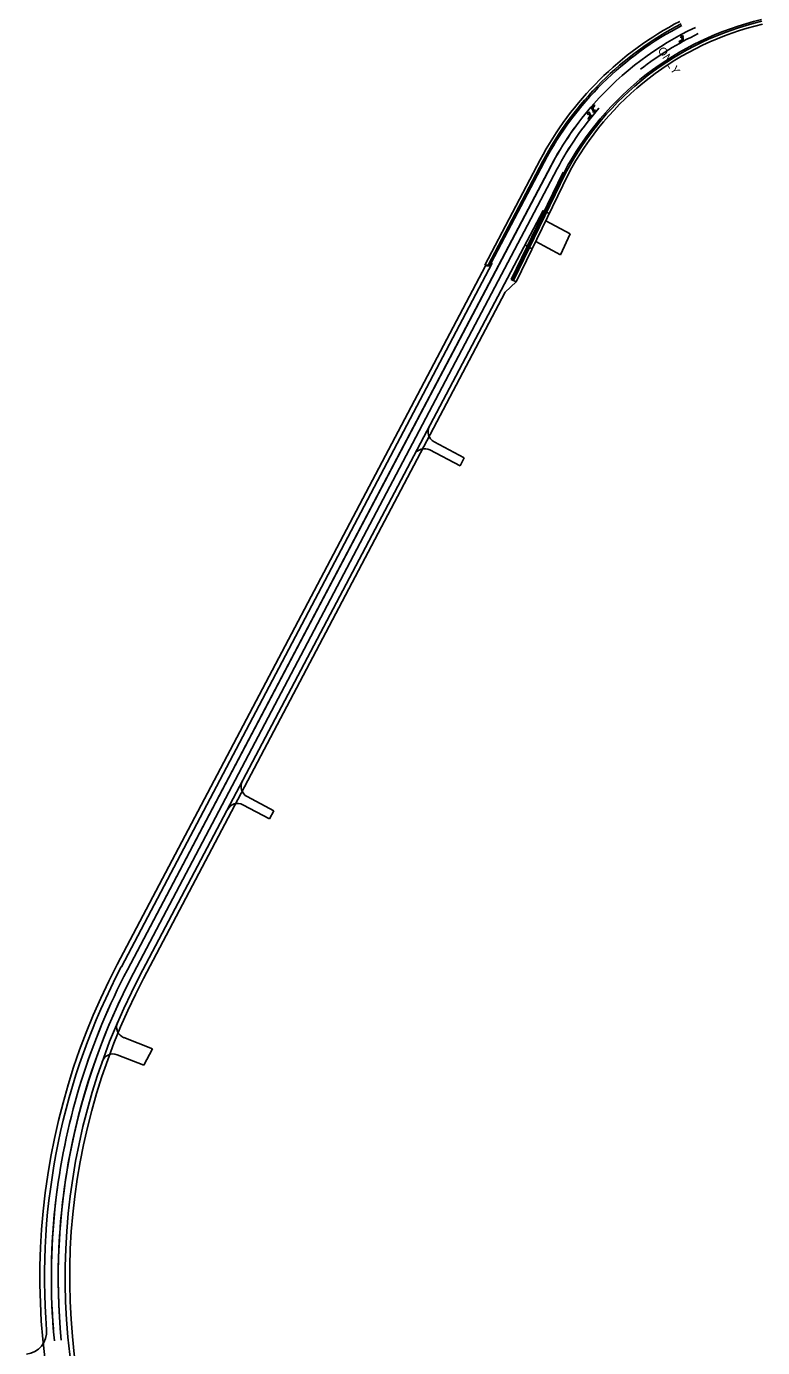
# Model space of a CAD drawing. Extents: x 979036 to 996074, y 1836928 to 1845163.
# Drawn here: x 980536 to 981821, y 1839457 to 1841763 of the extents above; entities that cross this region are included whole.
import ezdxf

# ---------------------------------------------------------------- set-up
doc = ezdxf.new("R2010")
doc.units = 0
for name, color, linetype in [('R_Proposed Road', 7, 'Continuous'), ('STRIPE_White Turn Arrow', 7, 'Continuous'), ('STRIPE_White_6in', 7, 'Continuous'), ('STRIPE_White_ONLY', 7, 'Continuous'), ('STRIPE_Yellow Dbl 6in', 7, 'Continuous'), ('STRIPE_Yellow_10_30 SKIP', 7, 'Continuous')]:
    doc.layers.add(name, color=color, linetype=linetype)

msp = doc.modelspace()

# ---------------------------------------------------------------- linework, layer by layer
at = {"layer": 'R_Proposed Road'}
for p, q in [((981432.6, 1841529.8), (981335.6, 1841345.8)), ((981437, 1841527.4), (981341.6, 1841346.3)), ((981439.6, 1841526.1), (981347.1, 1841350.4)), ((981472.8, 1841508.6), (981382.1, 1841321.3)), ((981383.4, 1841320.6), (981474.1, 1841507.9)), ((981386, 1841319.2), (981476.8, 1841506.5)), ((981390.5, 1841316.9), (981481.2, 1841504.1)), ((981448.2, 1841436), (981437.5, 1841441.6)), ((981484.6, 1841401), (981442.1, 1841423.4)), ((981484.6, 1841401), (981468.2, 1841364.4)), ((981418.5, 1841374.7), (981405.8, 1841381.4)), ((981468.2, 1841364.4), (981424.6, 1841387.4)), ((981337, 1841345.2), (980694.3, 1840125.3)), ((981390.5, 1841316.9), (981371.3, 1841298.7)), ((981382.1, 1841321.3), (981390.5, 1841316.9)), ((981371.3, 1841298.7), (980740.3, 1840101.1)), ((981300, 1841009.9), (981247.3, 1841037.7)), ((981292.9, 1840995.6), (981239.9, 1841023.5)), ((981292.9, 1840995.6), (981300, 1841009.9)), ((980967.8, 1840393.8), (980959.8, 1840379.9)), ((980755.9, 1839978.1), (980705.9, 1839997.7)), ((980740.5, 1839949.7), (980694.2, 1839967.9)), ((980755.9, 1839978.1), (980740.5, 1839949.7))]:
    msp.add_line(p, q, dxfattribs=at)
for points in [[(980959.8, 1840379.9), (980913.6, 1840404.2)], [(980967.8, 1840393.8), (980921.1, 1840418.4)]]:
    msp.add_lwpolyline(points, dxfattribs=at)
for centre, radius, start, end in [((981939.7, 1841262.6), 573.2, 117.3743, 152.2175), ((981939.7, 1841262.6), 568.2, 117.3743, 152.2175), ((981939.7, 1841262.6), 565.2, 117.3743, 152.2175), ((981939.7, 1841262.6), 526.2, 103.2783, 152.2175), ((981939.7, 1841262.6), 523.2, 103.2783, 152.2175), ((981939.7, 1841262.6), 518.2, 103.2783, 152.2175), ((981340, 1841354.2), 9.5, 242.2175, 332.2175), ((981340, 1841354.2), 8, 242.2175, 332.2175), ((981256.7, 1841055.4), 20, 152.2175, 242.2175), ((981230.6, 1841005.8), 20, 62.2175, 152.2175), ((980930.4, 1840436.1), 20, 152.2175, 242.2175), ((980904.3, 1840386.5), 20, 62.2175, 152.2175), ((981731.1, 1839579.1), 1171.9, 152.2175, 253.1679), ((981731.1, 1839579.1), 1119.9, 152.2175, 253.1679), ((980713.1, 1840016.3), 20, 156.7579, 248.62), ((980686.9, 1839949.2), 20, 68.62, 160.482)]:
    msp.add_arc(centre, radius, start, end, dxfattribs=at)
at = {"layer": 'STRIPE_White Turn Arrow'}
for points in [[(981678.2, 1841742.7), (981678.4, 1841747.1), (981682.6, 1841745.7), (981681.2, 1841744.8), (981681.6, 1841744.2), (981681.8, 1841743.7), (981682, 1841742.9), (981682.2, 1841741.9), (981682.2, 1841741.1), (981682, 1841740.3), (981681.8, 1841739.4), (981681.4, 1841738.7), (981680.9, 1841737.9), (981680.2, 1841737.3), (981679.5, 1841736.6), (981676, 1841734.8), (981675.1, 1841736.6), (981678.2, 1841738.3), (981678.8, 1841738.7), (981679.3, 1841739.2), (981679.8, 1841739.9), (981680.1, 1841740.7), (981680.2, 1841741.1), (981680.2, 1841741.8), (981680, 1841742.6), (981679.8, 1841743.3), (981679.6, 1841743.7)], [(981527.5, 1841617.8), (981529.2, 1841613.8), (981524.9, 1841613.1), (981525.7, 1841614.6), (981525.1, 1841615), (981524.7, 1841615.3), (981524.1, 1841615.9), (981523.6, 1841616.8), (981523.2, 1841617.5), (981523, 1841618.3), (981522.8, 1841619.2), (981522.9, 1841620), (981523, 1841620.9), (981523.3, 1841621.8), (981523.7, 1841622.7), (981526, 1841625.8), (981527.6, 1841624.7), (981525.5, 1841621.7), (981525.2, 1841621.2), (981524.9, 1841620.4), (981524.8, 1841619.6), (981524.9, 1841618.7), (981525, 1841618.4), (981525.3, 1841617.7), (981525.8, 1841617.1), (981526.3, 1841616.6), (981526.7, 1841616.3)], [(981516.2, 1841608.3), (981514.5, 1841612.3), (981518.8, 1841612.9), (981518, 1841611.5), (981518.5, 1841611.1), (981519, 1841610.7), (981519.6, 1841610.2), (981520.1, 1841609.3), (981520.5, 1841608.6), (981520.7, 1841607.8), (981520.9, 1841606.9), (981520.8, 1841606.1), (981520.7, 1841605.2), (981520.4, 1841604.3), (981520, 1841603.4), (981517.7, 1841600.2), (981516.1, 1841601.4), (981518.2, 1841604.3), (981518.5, 1841604.9), (981518.8, 1841605.6), (981518.9, 1841606.5), (981518.8, 1841607.4), (981518.7, 1841607.7), (981518.4, 1841608.4), (981517.9, 1841609), (981517.3, 1841609.5), (981517, 1841609.7)]]:
    msp.add_lwpolyline(points, close=True, dxfattribs=at)
at = {"layer": 'STRIPE_White_6in'}
for p, q in [((981437.5, 1841441.6), (980733.3, 1840104.8)), ((981348.4, 1841349.7), (980701.4, 1840121.6))]:
    msp.add_line(p, q, dxfattribs=at)
for centre, radius, start, end in [((981939.7, 1841262.6), 539.7, 115.3644, 127.991), ((981731.1, 1839579.1), 1163.9, 152.2175, 184.4896), ((981731.1, 1839579.1), 1127.9, 152.2175, 253.1679), ((980530.9, 1839484.8), 40, 276.8699, 4.4896)]:
    msp.add_arc(centre, radius, start, end, dxfattribs=at)
at = {"layer": 'STRIPE_Yellow Dbl 6in'}
msp.add_arc((981939.7, 1841262.6), 551.7, 115.3644, 138.5522, dxfattribs=at)
at = {"layer": 'STRIPE_Yellow_10_30 SKIP'}
for p, q in [((980712, 1840116), (981451.6, 1841519.8)), ((981451.6, 1841519.7), (980712, 1840116)), ((981462.2, 1841514.2), (980722.6, 1840110.4)), ((981462.2, 1841514.1), (980722.6, 1840110.4))]:
    msp.add_line(p, q, dxfattribs=at)
for centre, radius, start, end in [((981939.7, 1841262.6), 551.7, 138.5522, 152.2175), ((981939.6, 1841262.6), 551.7, 138.5522, 152.2175), ((981939.7, 1841262.6), 539.7, 138.5522, 152.2175), ((981939.6, 1841262.6), 539.7, 138.5522, 152.2175), ((981731.1, 1839579.1), 1151.9, 152.2175, 173.0008), ((981731.1, 1839579), 1151.9, 152.2175, 173.0008), ((981731.1, 1839579.1), 1139.9, 152.2175, 185.5159), ((981731.1, 1839579), 1139.9, 152.2175, 184.4608), ((981731.1, 1839579.1), 1151.9, 173.0008, 185.5159), ((981731.1, 1839579), 1151.9, 173.0008, 184.4896)]:
    msp.add_arc(centre, radius, start, end, dxfattribs=at)

# ---------------------------------------------------------------- texts
at = {"layer": 'STRIPE_White_ONLY'}
msp.add_text('ONLY', height=14.4, rotation=303.1099, dxfattribs=at).set_placement((981636.9, 1841721.3))

doc.saveas('drawing.dxf')
